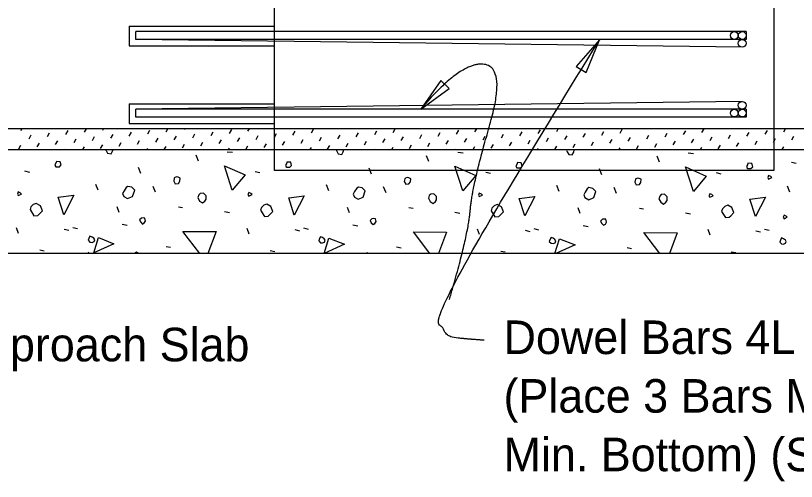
# Model space of a CAD drawing. Extents: x 21587 to 21659.1, y 56116.2 to 56157.3.
# Drawn here: x 21619.295 to 21623.985, y 56131.933 to 56134.73 of the extents above; entities that cross this region are included whole.
import ezdxf

# ---------------------------------------------------------------- set-up
doc = ezdxf.new("R2010")
doc.units = 0
for name, color, linetype in [('AdhocPoint_dp', 7, 'Continuous'), ('PlotBorder_dp', 7, 'Continuous'), ('SheetBorder_dp', 7, 'Continuous'), ('SheetLines_dp', 7, 'Continuous'), ('SubStrConc', 7, 'Continuous'), ('SubStrConc_h', 7, 'Continuous'), ('TextMisc', 7, 'Continuous')]:
    doc.layers.add(name, color=color, linetype=linetype)

msp = doc.modelspace()

# ---------------------------------------------------------------- linework, layer by layer
at = {"layer": 'AdhocPoint_dp'}
for p, q in [((21619.9783, 56134.6672), (21620.8503, 56134.6672)), ((21619.9783, 56134.6672), (21619.9783, 56134.5494)), ((21619.9783, 56134.5494), (21620.8503, 56134.5494)), ((21619.9783, 56134.2011), (21620.8503, 56134.2011)), ((21619.9783, 56134.2011), (21619.9783, 56134.0833)), ((21619.9783, 56134.0833), (21620.8503, 56134.0833)), ((21624.3563, 56134.0511), (21613.608, 56134.0511)), ((21613.608, 56133.926), (21624.3563, 56133.926)), ((21624.3563, 56133.301), (21618.8279, 56133.301))]:
    msp.add_line(p, q, dxfattribs=at)
at = {"layer": 'PlotBorder_dp'}
for points in [[(21622.8017, 56134.584), (21622.662, 56134.4255), (21622.722, 56134.3883)], [(21621.7288, 56134.1683), (21621.8998, 56134.2921), (21621.8495, 56134.3416)]]:
    msp.add_lwpolyline(points, close=True, dxfattribs=at)
for points in [[(21622.109, 56132.7809), (21621.9358, 56132.7915), (21621.8722, 56132.8163), (21621.805, 56132.9754), (21622.8016, 56134.584)], [(21621.9009, 56133.0246), (21622.0135, 56133.4067), (21622.0391, 56133.7156), (21622.2458, 56134.4216), (21621.9707, 56134.4548), (21621.7288, 56134.1683)]]:
    msp.add_open_spline(points, degree=2, dxfattribs=at)
at = {"layer": 'SheetLines_dp'}
for p, q in [((21623.6832, 56134.6343), (21620.0166, 56134.6343)), ((21620.0166, 56134.5874), (21620.0166, 56134.6343)), ((21623.6832, 56134.6343), (21623.6832, 56134.5874)), ((21623.6832, 56134.5874), (21620.0166, 56134.5874)), ((21623.6598, 56134.5406), (21620.0166, 56134.5874)), ((21623.6598, 56134.2152), (21620.0166, 56134.1683)), ((21623.6832, 56134.1683), (21620.0166, 56134.1683)), ((21620.0166, 56134.1214), (21620.0166, 56134.1683)), ((21623.6832, 56134.1683), (21623.6832, 56134.1214)), ((21623.6832, 56134.1214), (21620.0166, 56134.1214))]:
    msp.add_line(p, q, dxfattribs=at)
for centre in [(21623.6129, 56134.6109), (21623.6598, 56134.6109), (21623.6598, 56134.564), (21623.6598, 56134.1917), (21623.6129, 56134.1449), (21623.6598, 56134.1449)]:
    msp.add_circle(centre, 0.0234, dxfattribs=at)
at = {"layer": 'SubStrConc'}
for p, q in [((21620.8499, 56134.0509), (21620.8499, 56134.8009)), ((21623.8499, 56134.8009), (21623.8499, 56134.0509))]:
    msp.add_line(p, q, dxfattribs=at)
at = {"layer": 'SubStrConc_h'}
msp.add_lwpolyline([(21623.8499, 56134.0509), (21623.8499, 56133.8009), (21620.8499, 56133.8009), (21620.8499, 56134.0509)], dxfattribs=at)
at = {"layer": 'TextMisc'}
for p, q in [((21619.3275, 56134.04), (21619.3339, 56134.0511)), ((21619.5976, 56134.0171), (21619.6105, 56134.0395)), ((21619.7082, 56134.0301), (21619.7204, 56134.0511)), ((21619.8188, 56134.0431), (21619.8235, 56134.0511)), ((21620.0889, 56134.0202), (21620.1019, 56134.0426)), ((21620.1996, 56134.0331), (21620.21, 56134.0511)), ((21620.3102, 56134.0461), (21620.3131, 56134.0511)), ((21620.5803, 56134.0232), (21620.5933, 56134.0456)), ((21620.6909, 56134.0361), (21620.6996, 56134.0511)), ((21620.8016, 56134.0491), (21620.8027, 56134.0511)), ((21620.961, 56134.0132), (21620.974, 56134.0356)), ((21621.0717, 56134.0262), (21621.0846, 56134.0486)), ((21621.4524, 56134.0163), (21621.4654, 56134.0386)), ((21621.563, 56134.0292), (21621.5757, 56134.0511)), ((21621.9438, 56134.0193), (21621.9567, 56134.0417)), ((21622.0544, 56134.0322), (21622.0653, 56134.0511)), ((21622.4351, 56134.0223), (21622.4481, 56134.0447)), ((21622.5458, 56134.0353), (21622.5549, 56134.0511)), ((21622.8159, 56134.0124), (21622.8288, 56134.0347)), ((21622.9265, 56134.0253), (21622.9395, 56134.0477)), ((21623.3072, 56134.0154), (21623.3202, 56134.0378)), ((21623.4179, 56134.0283), (21623.4308, 56134.0507)), ((21623.7986, 56134.0184), (21623.8116, 56134.0408)), ((21623.9092, 56134.0314), (21623.9206, 56134.0511)), ((21619.3763, 56133.9912), (21619.3893, 56134.0136)), ((21619.4869, 56134.0042), (21619.4999, 56134.0266)), ((21619.6464, 56133.9683), (21619.6594, 56133.9907)), ((21619.757, 56133.9813), (21619.77, 56134.0037)), ((21619.8677, 56133.9942), (21619.8806, 56134.0166)), ((21619.9783, 56134.0072), (21619.9913, 56134.0296)), ((21620.1378, 56133.9713), (21620.1507, 56133.9937)), ((21620.2484, 56133.9843), (21620.2614, 56134.0067)), ((21620.359, 56133.9973), (21620.372, 56134.0196)), ((21620.4697, 56134.0102), (21620.4826, 56134.0326)), ((21620.6291, 56133.9743), (21620.6421, 56133.9967)), ((21620.7398, 56133.9873), (21620.7527, 56134.0097)), ((21620.8504, 56134.0003), (21620.8634, 56134.0227)), ((21621.1205, 56133.9774), (21621.1335, 56133.9998)), ((21621.2311, 56133.9903), (21621.2441, 56134.0127)), ((21621.3418, 56134.0033), (21621.3547, 56134.0257)), ((21621.5012, 56133.9674), (21621.5142, 56133.9898)), ((21621.6119, 56133.9804), (21621.6248, 56134.0028)), ((21621.7225, 56133.9933), (21621.7355, 56134.0157)), ((21621.8331, 56134.0063), (21621.8461, 56134.0287)), ((21621.9926, 56133.9704), (21622.0056, 56133.9928)), ((21622.1032, 56133.9834), (21622.1162, 56134.0058)), ((21622.2139, 56133.9964), (21622.2268, 56134.0188)), ((21622.3245, 56134.0093), (21622.3375, 56134.0317)), ((21622.484, 56133.9735), (21622.4969, 56133.9959)), ((21622.5946, 56133.9864), (21622.6076, 56134.0088)), ((21622.7052, 56133.9994), (21622.7182, 56134.0218)), ((21622.9753, 56133.9765), (21622.9883, 56133.9989)), ((21623.086, 56133.9894), (21623.0989, 56134.0118)), ((21623.1966, 56134.0024), (21623.2096, 56134.0248)), ((21623.3561, 56133.9665), (21623.369, 56133.9889)), ((21623.4667, 56133.9795), (21623.4797, 56134.0019)), ((21623.5773, 56133.9925), (21623.5903, 56134.0149)), ((21623.688, 56134.0054), (21623.7009, 56134.0278)), ((21623.8474, 56133.9696), (21623.8604, 56133.9919)), ((21623.9571, 56133.9838), (21623.97, 56134.0062)), ((21619.3145, 56133.9294), (21619.3275, 56133.9518)), ((21619.4251, 56133.9424), (21619.4381, 56133.9648)), ((21619.5358, 56133.9553), (21619.5487, 56133.9777)), ((21619.699, 56133.926), (21619.7082, 56133.9419)), ((21619.8059, 56133.9324), (21619.8188, 56133.9548)), ((21619.9165, 56133.9454), (21619.9295, 56133.9678)), ((21620.0271, 56133.9584), (21620.0401, 56133.9808)), ((21620.1886, 56133.926), (21620.1996, 56133.9449)), ((21620.2972, 56133.9355), (21620.3102, 56133.9578)), ((21620.4079, 56133.9484), (21620.4208, 56133.9708)), ((21620.5185, 56133.9614), (21620.5315, 56133.9838)), ((21620.6783, 56133.926), (21620.6909, 56133.9479)), ((21620.7886, 56133.9385), (21620.8016, 56133.9609)), ((21620.8992, 56133.9514), (21620.9122, 56133.9738)), ((21621.0099, 56133.9644), (21621.0228, 56133.9868)), ((21621.1693, 56133.9285), (21621.1823, 56133.9509)), ((21621.28, 56133.9415), (21621.2929, 56133.9639)), ((21621.3906, 56133.9545), (21621.4036, 56133.9768)), ((21621.5544, 56133.926), (21621.563, 56133.941)), ((21621.6607, 56133.9315), (21621.6737, 56133.9539)), ((21621.7713, 56133.9445), (21621.7843, 56133.9669)), ((21621.882, 56133.9575), (21621.8949, 56133.9799)), ((21622.044, 56133.926), (21622.0544, 56133.944)), ((21622.1521, 56133.9346), (21622.165, 56133.957)), ((21622.2627, 56133.9475), (21622.2757, 56133.9699)), ((21622.3733, 56133.9605), (21622.3863, 56133.9829)), ((21622.5336, 56133.926), (21622.5458, 56133.947)), ((21622.6434, 56133.9376), (21622.6564, 56133.96)), ((21622.7541, 56133.9506), (21622.767, 56133.9729)), ((21622.8647, 56133.9635), (21622.8777, 56133.9859)), ((21623.0242, 56133.9276), (21623.0371, 56133.95)), ((21623.1348, 56133.9406), (21623.1478, 56133.963)), ((21623.2454, 56133.9536), (21623.2584, 56133.976)), ((21623.5155, 56133.9307), (21623.5285, 56133.9531)), ((21623.6262, 56133.9436), (21623.6391, 56133.966)), ((21623.7368, 56133.9566), (21623.7498, 56133.979)), ((21623.8993, 56133.926), (21623.9092, 56133.9431)), ((21619.5959, 56133.926), (21619.5976, 56133.9289)), ((21620.0855, 56133.926), (21620.0889, 56133.9319)), ((21620.5663, 56133.913), (21620.5981, 56133.9094)), ((21620.5751, 56133.926), (21620.5803, 56133.9349)), ((21621.0648, 56133.926), (21621.0717, 56133.938)), ((21621.4512, 56133.926), (21621.4524, 56133.928)), ((21621.9409, 56133.926), (21621.9438, 56133.931)), ((21621.951, 56133.9094), (21621.9828, 56133.9059)), ((21622.4305, 56133.926), (21622.4351, 56133.9341)), ((21622.9201, 56133.926), (21622.9265, 56133.9371)), ((21623.3066, 56133.926), (21623.3072, 56133.9271)), ((21623.3356, 56133.9059), (21623.3675, 56133.9024)), ((21623.4097, 56133.926), (21623.4179, 56133.9401)), ((21623.7962, 56133.926), (21623.7986, 56133.9302)), ((21620.3937, 56133.857), (21620.3795, 56133.8924)), ((21621.7784, 56133.8535), (21621.7642, 56133.8889)), ((21623.163, 56133.85), (21623.1489, 56133.8853)), ((21623.9556, 56133.8507), (21623.9839, 56133.8437)), ((21620.0478, 56133.7822), (21620.0337, 56133.8175)), ((21621.4325, 56133.7786), (21621.4184, 56133.814)), ((21622.8172, 56133.7751), (21622.803, 56133.8104)), ((21619.3496, 56133.7981), (21619.3778, 56133.791)), ((21620.7342, 56133.7945), (21620.7625, 56133.7875)), ((21622.1189, 56133.791), (21622.1472, 56133.7839)), ((21623.5036, 56133.7875), (21623.5319, 56133.7804)), ((21619.7915, 56133.6814), (21619.7774, 56133.7168)), ((21621.1762, 56133.6779), (21621.162, 56133.7132)), ((21622.5609, 56133.6743), (21622.5467, 56133.7097)), ((21623.9455, 56133.6708), (21623.9314, 56133.7062)), ((21620.1356, 56133.6697), (21620.1214, 56133.705)), ((21621.5203, 56133.6661), (21621.5061, 56133.7015)), ((21622.9049, 56133.6626), (21622.8908, 56133.6979)), ((21619.917, 56133.5488), (21619.9046, 56133.5824)), ((21620.2735, 56133.5813), (21620.2982, 56133.5777)), ((21621.3017, 56133.5453), (21621.2893, 56133.5789)), ((21621.6581, 56133.5777), (21621.6829, 56133.5742)), ((21622.6864, 56133.5417), (21622.674, 56133.5753)), ((21623.0428, 56133.5742), (21623.0676, 56133.5707)), ((21620.5492, 56133.553), (21620.5793, 56133.5477)), ((21621.9339, 56133.5494), (21621.964, 56133.5441)), ((21623.3186, 56133.5459), (21623.3486, 56133.5406)), ((21619.9358, 56133.477), (21619.9659, 56133.4717)), ((21621.3205, 56133.4734), (21621.3506, 56133.4681)), ((21619.3131, 56133.4222), (21619.3007, 56133.4558)), ((21619.5871, 56133.4487), (21619.6153, 56133.4416)), ((21619.6395, 56133.4587), (21619.6678, 56133.4516)), ((21620.6977, 56133.4186), (21620.6854, 56133.4522)), ((21620.9717, 56133.4451), (21621, 56133.4381)), ((21621.0241, 56133.4551), (21621.0524, 56133.4481)), ((21622.0824, 56133.4151), (21622.07, 56133.4487)), ((21622.3564, 56133.4416), (21622.3847, 56133.4345)), ((21622.4088, 56133.4516), (21622.4371, 56133.4445)), ((21622.7052, 56133.4699), (21622.7352, 56133.4646)), ((21623.4671, 56133.4116), (21623.4547, 56133.4451)), ((21623.7411, 56133.4381), (21623.7694, 56133.431)), ((21623.7935, 56133.4481), (21623.8218, 56133.441)), ((21620.1992, 56133.3444), (21620.2257, 56133.3391)), ((21621.5839, 56133.3408), (21621.6104, 56133.3355)), ((21622.9686, 56133.3373), (21622.9951, 56133.332)), ((21619.4403, 56133.3232), (21619.4669, 56133.3179)), ((21619.7364, 56133.301), (21619.7332, 56133.3097)), ((21620.825, 56133.3196), (21620.8515, 56133.3143)), ((21621.1197, 56133.301), (21621.1178, 56133.3061)), ((21622.2097, 56133.3161), (21622.2362, 56133.3108)), ((21622.5031, 56133.301), (21622.5025, 56133.3026)), ((21623.5944, 56133.3126), (21623.6209, 56133.3073))]:
    msp.add_line(p, q, dxfattribs=at)
for points in [[(21619.8362, 56133.926), (21619.8392, 56133.9201)], [(21619.8392, 56133.9201), (21619.8481, 56133.9041), (21619.8693, 56133.9006), (21619.8781, 56133.9165), (21619.8805, 56133.926)], [(21621.2212, 56133.926), (21621.2204, 56133.9236), (21621.2239, 56133.9165)], [(21621.2239, 56133.9165), (21621.2327, 56133.9006), (21621.254, 56133.8971), (21621.2628, 56133.913), (21621.2661, 56133.926)], [(21622.607, 56133.926), (21622.605, 56133.9201), (21622.6086, 56133.913)], [(21622.6086, 56133.913), (21622.6174, 56133.8971), (21622.6386, 56133.8935), (21622.6475, 56133.9094), (21622.651, 56133.9236), (21622.6486, 56133.926)], [(21619.5369, 56133.8228), (21619.5582, 56133.8228), (21619.5688, 56133.8334), (21619.5635, 56133.8529), (21619.5405, 56133.8546), (21619.5369, 56133.844), (21619.5316, 56133.8352), (21619.5369, 56133.8228), (21619.5334, 56133.8264)], [(21620.9216, 56133.8193), (21620.9428, 56133.8193), (21620.9534, 56133.8299), (21620.9481, 56133.8493), (21620.9252, 56133.8511), (21620.9216, 56133.8405), (21620.9163, 56133.8317), (21620.9216, 56133.8193), (21620.9181, 56133.8228)], [(21622.3063, 56133.8158), (21622.3275, 56133.8158), (21622.3381, 56133.8264), (21622.3328, 56133.8458), (21622.3098, 56133.8476), (21622.3063, 56133.837), (21622.301, 56133.8281), (21622.3063, 56133.8158), (21622.3028, 56133.8193)], [(21620.597, 56133.682), (21620.5492, 56133.8288), (21620.6748, 56133.774), (21620.597, 56133.682)], [(21621.9816, 56133.6785), (21621.9339, 56133.8252), (21622.0594, 56133.7704), (21621.9816, 56133.6785)], [(21623.3663, 56133.675), (21623.3186, 56133.8217), (21623.4441, 56133.7669), (21623.3663, 56133.675)], [(21623.691, 56133.8122), (21623.7122, 56133.8122), (21623.7228, 56133.8228), (21623.7175, 56133.8423), (21623.6945, 56133.844), (21623.691, 56133.8334), (21623.6857, 56133.8246), (21623.691, 56133.8122), (21623.6874, 56133.8158)], [(21620.2452, 56133.7368), (21620.254, 56133.7209), (21620.2735, 56133.7227), (21620.2823, 56133.7351), (21620.2841, 56133.7545), (21620.2717, 56133.7598), (21620.2629, 56133.7616), (21620.2523, 56133.758), (21620.2487, 56133.7545), (21620.2452, 56133.7368)], [(21621.6299, 56133.7333), (21621.6387, 56133.7174), (21621.6581, 56133.7192), (21621.667, 56133.7315), (21621.6688, 56133.751), (21621.6564, 56133.7563), (21621.6475, 56133.758), (21621.6369, 56133.7545), (21621.6334, 56133.751), (21621.6299, 56133.7333)], [(21623.0145, 56133.7298), (21623.0234, 56133.7138), (21623.0428, 56133.7156), (21623.0517, 56133.728), (21623.0534, 56133.7474), (21623.0411, 56133.7527), (21623.0322, 56133.7545), (21623.0216, 56133.751), (21623.0181, 56133.7474), (21623.0145, 56133.7298)], [(21623.8185, 56133.7486), (21623.8379, 56133.7574), (21623.8308, 56133.7645), (21623.8185, 56133.7698), (21623.8132, 56133.7574), (21623.8185, 56133.7486)], [(21619.3113, 56133.6502), (21619.3307, 56133.659), (21619.3237, 56133.6661), (21619.3113, 56133.6714), (21619.306, 56133.659), (21619.3113, 56133.6502)], [(21619.9453, 56133.6443), (21619.9683, 56133.6319), (21619.9983, 56133.6443), (21620.0107, 56133.6814), (21619.993, 56133.6991), (21619.97, 56133.7044), (21619.9594, 56133.6973), (21619.9471, 56133.6779), (21619.9382, 56133.662), (21619.9453, 56133.6443)], [(21620.3901, 56133.6378), (21620.4008, 56133.6166), (21620.4184, 56133.606), (21620.4326, 56133.6166), (21620.4396, 56133.6272), (21620.4396, 56133.6484), (21620.4237, 56133.6644), (21620.4043, 56133.6626), (21620.3954, 56133.6537), (21620.3901, 56133.6378)], [(21620.696, 56133.6467), (21620.7154, 56133.6555), (21620.7083, 56133.6626), (21620.696, 56133.6679), (21620.6907, 56133.6555), (21620.696, 56133.6467)], [(21621.33, 56133.6407), (21621.353, 56133.6284), (21621.383, 56133.6407), (21621.3954, 56133.6779), (21621.3777, 56133.6955), (21621.3547, 56133.7008), (21621.3441, 56133.6938), (21621.3317, 56133.6743), (21621.3229, 56133.6584), (21621.33, 56133.6407)], [(21621.7748, 56133.6343), (21621.7854, 56133.6131), (21621.8031, 56133.6025), (21621.8172, 56133.6131), (21621.8243, 56133.6237), (21621.8243, 56133.6449), (21621.8084, 56133.6608), (21621.789, 56133.659), (21621.7801, 56133.6502), (21621.7748, 56133.6343)], [(21622.0806, 56133.6431), (21622.1001, 56133.652), (21622.093, 56133.659), (21622.0806, 56133.6644), (21622.0753, 56133.652), (21622.0806, 56133.6431)], [(21622.7146, 56133.6372), (21622.7376, 56133.6248), (21622.7677, 56133.6372), (21622.7801, 56133.6743), (21622.7624, 56133.692), (21622.7394, 56133.6973), (21622.7288, 56133.6902), (21622.7164, 56133.6708), (21622.7076, 56133.6549), (21622.7146, 56133.6372)], [(21623.4653, 56133.6396), (21623.4848, 56133.6484), (21623.4777, 56133.6555), (21623.4653, 56133.6608), (21623.46, 56133.6484), (21623.4653, 56133.6396)], [(21619.5847, 56133.5347), (21619.5511, 56133.639), (21619.6448, 56133.6514), (21619.5847, 56133.5347)], [(21620.9693, 56133.5311), (21620.9358, 56133.6354), (21621.0294, 56133.6478), (21620.9693, 56133.5311)], [(21622.354, 56133.5276), (21622.3204, 56133.6319), (21622.4141, 56133.6443), (21622.354, 56133.5276)], [(21623.1595, 56133.6308), (21623.1701, 56133.6096), (21623.1878, 56133.5989), (21623.2019, 56133.6096), (21623.209, 56133.6202), (21623.209, 56133.6414), (21623.1931, 56133.6573), (21623.1736, 56133.6555), (21623.1648, 56133.6467), (21623.1595, 56133.6308)], [(21623.7387, 56133.5241), (21623.7051, 56133.6284), (21623.7988, 56133.6407), (21623.7387, 56133.5241)], [(21619.382, 56133.5654), (21619.405, 56133.5282), (21619.428, 56133.53), (21619.4368, 56133.5388), (21619.4562, 56133.5583), (21619.4439, 56133.5883), (21619.4191, 56133.6025), (21619.4014, 56133.5954), (21619.3873, 56133.5813), (21619.382, 56133.5654)], [(21620.7667, 56133.5618), (21620.7897, 56133.5247), (21620.8126, 56133.5265), (21620.8215, 56133.5353), (21620.8409, 56133.5547), (21620.8285, 56133.5848), (21620.8038, 56133.5989), (21620.7861, 56133.5919), (21620.772, 56133.5777), (21620.7667, 56133.5618)], [(21622.1514, 56133.5583), (21622.1743, 56133.5212), (21622.1973, 56133.5229), (21622.2062, 56133.5318), (21622.2256, 56133.5512), (21622.2132, 56133.5813), (21622.1885, 56133.5954), (21622.1708, 56133.5883), (21622.1567, 56133.5742), (21622.1514, 56133.5583)], [(21623.536, 56133.5547), (21623.559, 56133.5176), (21623.582, 56133.5194), (21623.5908, 56133.5282), (21623.6103, 56133.5477), (21623.5979, 56133.5777), (21623.5732, 56133.5919), (21623.5555, 56133.5848), (21623.5413, 56133.5707), (21623.536, 56133.5547)], [(21623.9109, 56133.5108), (21623.9303, 56133.5197), (21623.9232, 56133.5267), (21623.9109, 56133.5321), (21623.9056, 56133.5197), (21623.9109, 56133.5108)], [(21620.0472, 56133.4893), (21620.0578, 56133.4787), (21620.0684, 56133.4858), (21620.0755, 56133.4964), (21620.0719, 56133.5141), (21620.0631, 56133.5159), (21620.0507, 56133.5141), (21620.0401, 56133.5035), (21620.0472, 56133.4893)], [(21621.4319, 56133.4858), (21621.4425, 56133.4752), (21621.4531, 56133.4823), (21621.4602, 56133.4929), (21621.4566, 56133.5106), (21621.4478, 56133.5123), (21621.4354, 56133.5106), (21621.4248, 56133.4999), (21621.4319, 56133.4858)], [(21622.8166, 56133.4823), (21622.8272, 56133.4717), (21622.8378, 56133.4787), (21622.8448, 56133.4893), (21622.8413, 56133.507), (21622.8325, 56133.5088), (21622.8201, 56133.507), (21622.8095, 56133.4964), (21622.8166, 56133.4823)], [(21620.4015, 56133.301), (21620.3, 56133.4345), (21620.4997, 56133.4328), (21620.4505, 56133.301)], [(21621.7835, 56133.301), (21621.6847, 56133.431), (21621.8844, 56133.4292), (21621.8365, 56133.301)], [(21623.1655, 56133.301), (21623.0693, 56133.4275), (21623.2691, 56133.4257), (21623.2225, 56133.301)], [(21619.742, 56133.3703), (21619.7544, 56133.3685), (21619.7667, 56133.3738), (21619.7703, 56133.3844), (21619.765, 56133.3933), (21619.7544, 56133.4003), (21619.742, 56133.4056), (21619.7349, 56133.3915), (21619.7314, 56133.3809), (21619.742, 56133.3703)], [(21619.7644, 56133.3055), (21619.7926, 56133.3974), (21619.8863, 56133.3603), (21619.7644, 56133.3055)], [(21621.1267, 56133.3667), (21621.1391, 56133.365), (21621.1514, 56133.3703), (21621.155, 56133.3809), (21621.1497, 56133.3897), (21621.1391, 56133.3968), (21621.1267, 56133.4021), (21621.1196, 56133.388), (21621.1161, 56133.3773), (21621.1267, 56133.3667)], [(21621.149, 56133.302), (21621.1773, 56133.3939), (21621.271, 56133.3568), (21621.149, 56133.302)], [(21622.5114, 56133.3632), (21622.5237, 56133.3614), (21622.5361, 56133.3667), (21622.5396, 56133.3773), (21622.5343, 56133.3862), (21622.5237, 56133.3933), (21622.5114, 56133.3986), (21622.5043, 56133.3844), (21622.5007, 56133.3738), (21622.5114, 56133.3632)], [(21622.5345, 56133.301), (21622.562, 56133.3903), (21622.6557, 56133.3532), (21622.5394, 56133.301)], [(21623.896, 56133.3597), (21623.9084, 56133.3579), (21623.9208, 56133.3632), (21623.9243, 56133.3738), (21623.919, 56133.3827), (21623.9084, 56133.3897), (21623.896, 56133.395), (21623.889, 56133.3809), (21623.8854, 56133.3703), (21623.896, 56133.3597)], [(21620.0368, 56133.301), (21620.0366, 56133.302), (21620.0224, 56133.309), (21620.009, 56133.301)], [(21621.4161, 56133.301), (21621.4071, 56133.3055), (21621.3996, 56133.301)], [(21622.7937, 56133.301), (21622.7918, 56133.302), (21622.7902, 56133.301)]]:
    msp.add_lwpolyline(points, dxfattribs=at)

# ---------------------------------------------------------------- texts
at = {"layer": 'PlotBorder_dp'}
for s, p in [('Dowel Bars 4L (10" Embedment) ', (21622.226, 56132.6977)), ('(Place 3 Bars Min. Top and 1 Bar ', (21622.226, 56132.3457)), ('Min. Bottom) (See Note 2)', (21622.226, 56131.9937))]:
    msp.add_text(s, height=0.2016, dxfattribs=at).set_placement(p)
at = {"layer": 'SheetBorder_dp'}
msp.add_text('Existing Approach Slab', height=0.2016, dxfattribs=at).set_placement((21617.9127, 56132.654))

doc.saveas('drawing.dxf')
